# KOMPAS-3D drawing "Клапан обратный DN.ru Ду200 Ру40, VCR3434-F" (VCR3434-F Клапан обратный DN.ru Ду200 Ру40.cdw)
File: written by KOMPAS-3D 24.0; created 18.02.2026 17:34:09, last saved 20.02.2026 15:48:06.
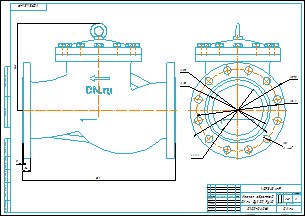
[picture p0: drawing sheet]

Document properties: art: D100-04061; Автор: R2D2; Форматы листов документа: A2; Полное имя файла: VCR3434-F Клапан обратный DN.ru Ду200 Ру40.m3d; Масса: 145; Наименование: Клапан обратный DN.ru Ду200 Ру40; Количество листов документа: 1; Примечание: D100-04061

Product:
- Part/product: Клапан обратный DN.ru Ду200 Ру40  | designation VCR3434-F
    Масса: 145
    Раздел спецификации: Прочие изделия
    Примечание: D100-04061
    additional columns: D100-04061

Views: Проекционный вид 2
Referenced files in E:\Работа\Зайцев\VCR3434-F Клапан обратный DN.ru Ду15-300\DN200\: VCR3434-F Клапан обратный DN.ru Ду200 Ру40.m3d
Referenced files in E:\Работа\Зайцев\Для компаса\: чертеж DN.ru А3.cdt
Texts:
  VCR3434-F
  чертеж DN.ru А3.cdt
  Клапан обратный
  DN.ru Ду200 Ру40
  prop
  Клапан обратный DN.ru Ду200 Ру40
  VCR3434-F Клапан обратный DN.ru Ду200 Ру40
Dimensions and other numbers on the sheet: 0; 3; 4; 340; 5; 34; 600; 1:2; 1; 2; 145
